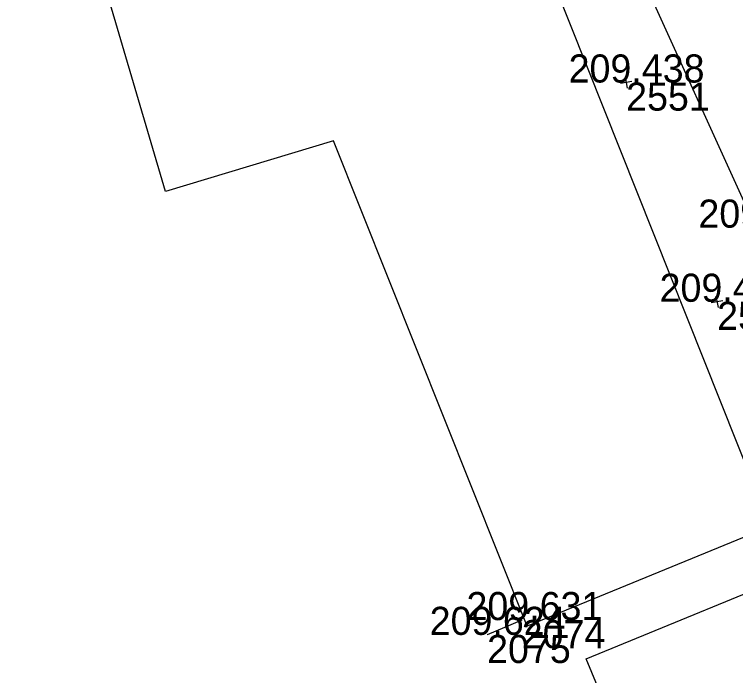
# Model space of a CAD drawing. Extents: x -556590 to -554855, y -1137918 to -1135717.
# Drawn here: x -555036.1 to -555005.33, y -1137275.32 to -1137247.09 of the extents above; entities that cross this region are included whole.
import ezdxf

# ---------------------------------------------------------------- set-up
doc = ezdxf.new("R2010")
doc.units = 0
for name, color, linetype in [('Vrstva 17', 7, 'Continuous'), ('Vrstva 23', 7, 'Continuous'), ('Vrstva 49', 7, 'Continuous'), ('Vrstva 51', 7, 'Continuous'), ('Vrstva 60', 7, 'Continuous'), ('Vrstva 61', 7, 'Continuous')]:
    doc.layers.add(name, color=color, linetype=linetype)

msp = doc.modelspace()

# ---------------------------------------------------------------- linework, layer by layer
at = {"layer": 'Vrstva 17'}
msp.add_line((-555014.455, -1137272.954), (-555015.932, -1137273.585), dxfattribs=at)
at = {"layer": 'Vrstva 23'}
for points in [[(-555032.785, -1137244.004), (-555016.825, -1137239.11), (-555015.227, -1137240.361), (-555003.854, -1137268.957), (-555014.22, -1137273.217), (-555022.49, -1137252.495), (-555029.662, -1137254.659), (-555032.785, -1137244.004)], [(-555001.443, -1137270.389), (-554994.396, -1137287.723), (-554996.287, -1137288.452), (-554990.752, -1137305.874), (-554993.395, -1137306.708), (-554992.699, -1137309.185), (-554997.164, -1137310.589), (-554997.913, -1137308.185), (-555000.641, -1137309.05), (-555006.14, -1137291.642), (-555004.803, -1137291.24), (-555011.71, -1137274.605), (-555001.443, -1137270.389)]]:
    msp.add_lwpolyline(points, dxfattribs=at)
at = {"layer": 'Vrstva 49'}
for p, q in [((-555010.047, -1137249.754), (-555009.953, -1137250.246)), ((-555009.754, -1137249.953), (-555010.246, -1137250.047)), ((-555005.871, -1137259.314), (-555006.363, -1137259.408)), ((-555006.164, -1137259.115), (-555006.07, -1137259.607))]:
    msp.add_line(p, q, dxfattribs=at)
at = {"layer": 'Vrstva 51'}
msp.add_lwpolyline([(-554992.789, -1137283.491), (-554996.889, -1137272.7), (-555000.207, -1137265.439), (-555004.464, -1137256.196), (-555009.574, -1137244.938), (-555011.759, -1137239.97), (-555012.421, -1137238.305), (-555013.148, -1137236.797), (-555013.681, -1137236.03), (-555014.422, -1137235.4), (-555015.187, -1137234.97), (-555016.04, -1137234.696), (-555016.783, -1137234.522), (-555017.525, -1137234.511), (-555018.162, -1137234.559), (-555020.081, -1137235), (-555030.011, -1137237.02), (-555029.953, -1137237.323), (-555030.492, -1137237.43), (-555030.559, -1137237.122), (-555036.105, -1137238.28)], dxfattribs=at)
at = {"layer": 'Vrstva 60'}
for p, q in [((-555010, -1137250), (-555010, -1137250)), ((-555006.117, -1137259.361), (-555006.117, -1137259.361)), ((-555014.455, -1137272.954), (-555014.455, -1137272.954)), ((-555015.932, -1137273.585), (-555015.932, -1137273.585))]:
    msp.add_line(p, q, dxfattribs=at)

# ---------------------------------------------------------------- texts
for s, p in [('2551', (-555010, -1137251.2)), ('2552', (-555006.117, -1137260.561)), ('2074', (-555014.455, -1137274.154)), ('2075', (-555015.932, -1137274.785))]:
    msp.add_text(s, height=1.2, dxfattribs=at).set_placement(p)
at = {"layer": 'Vrstva 61'}
for s, p in [('209.438', (-555012.454, -1137250)), ('209.424', (-555006.915, -1137256.196)), ('209.428', (-555008.571, -1137259.361)), ('209.631', (-555016.812, -1137272.954)), ('209.624', (-555018.383, -1137273.585))]:
    msp.add_text(s, height=1.2, dxfattribs=at).set_placement(p)

doc.saveas('drawing.dxf')
